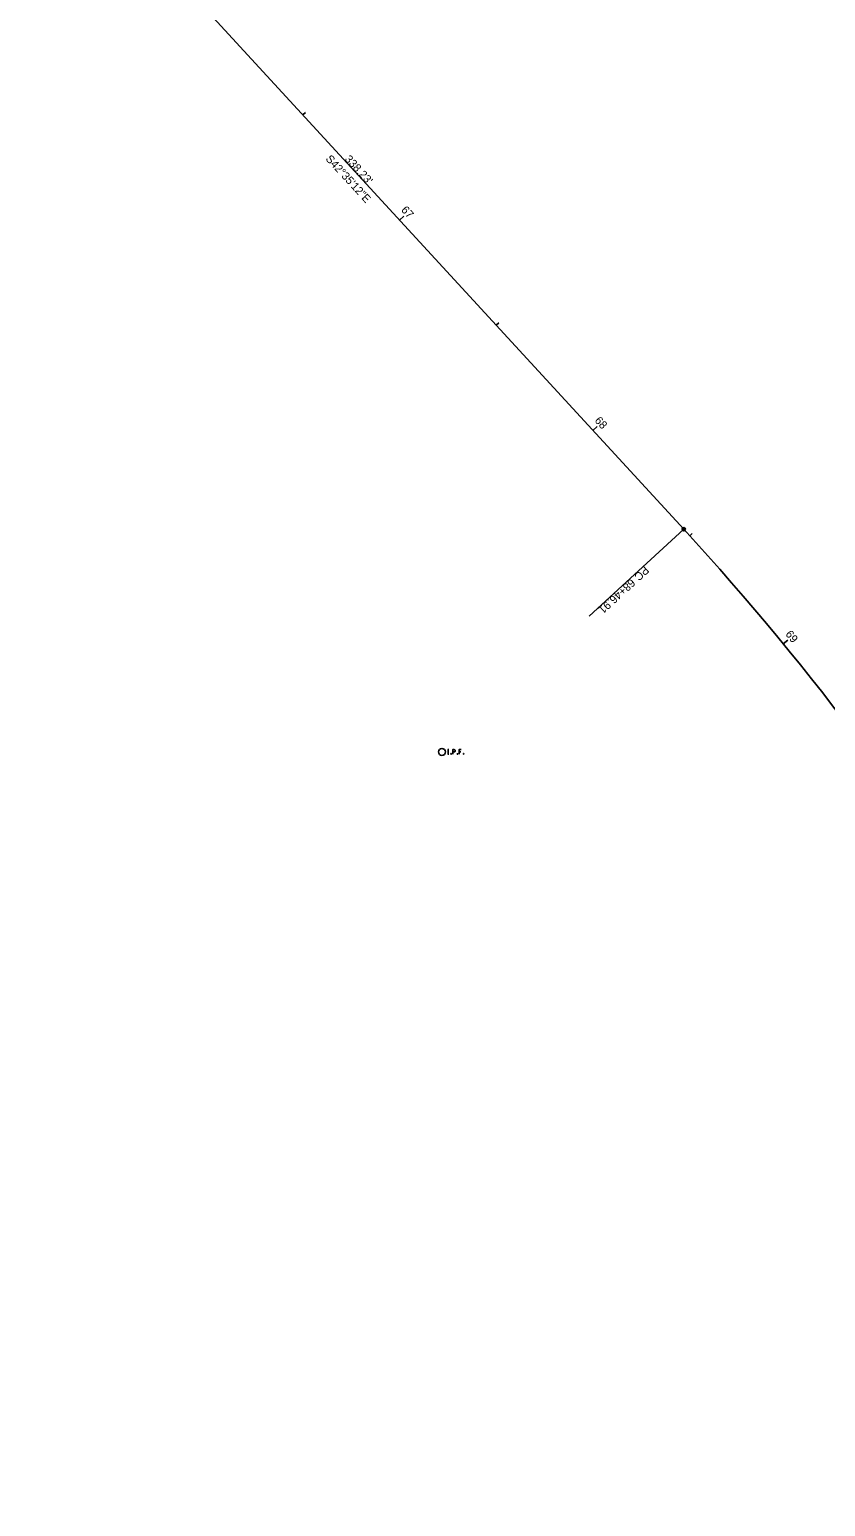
# Model space of a CAD drawing. Extents: x 1918148 to 1920349, y 624677 to 627727.
# Drawn here: x 1919025 to 1919304, y 624918 to 625435 of the extents above; entities that cross this region are included whole.
import ezdxf

# ---------------------------------------------------------------- set-up
doc = ezdxf.new("R2010")
doc.units = 0
for name, color, linetype in [('_CIVIL_CONSTRUCTION', 7, 'Continuous'), ('RS_Raster1', 7, 'Continuous'), ('RW_X_CL', 7, 'Continuous'), ('RW_X_CL_100_Cardinal_Points', 7, 'Continuous'), ('RW_X_CL_100_Curve_Data', 7, 'Continuous'), ('SV_X_Mon_Cells_Found', 7, 'Continuous')]:
    doc.layers.add(name, color=color, linetype=linetype)

msp = doc.modelspace()

# ---------------------------------------------------------------- linework, layer by layer
at = {"layer": 'RS_Raster1'}
msp.add_line((1919025.5, 625508.81), (1919254.38, 625259.79), dxfattribs=at)
msp.add_arc((1918551.3, 624613.58), 954.93, 18.58639, 42.58667, dxfattribs=at)
at = {"layer": 'RW_X_CL'}
msp.add_line((1919254.38, 625259.79), (1919221.25, 625229.34), dxfattribs=at)
msp.add_circle((1919254.38, 625259.79), 0.6, dxfattribs=at)
at = {"layer": 'RW_X_CL_100_Cardinal_Points'}
for p, q in [((1919121.13, 625404.76), (1919122.01, 625405.58)), ((1919154.96, 625367.95), (1919156.44, 625369.3)), ((1919188.8, 625331.14), (1919189.68, 625331.95)), ((1919222.63, 625294.33), (1919224.11, 625295.68)), ((1919256.47, 625257.51), (1919257.35, 625258.32)), ((1919289.2, 625219.72), (1919290.75, 625220.99))]:
    msp.add_line(p, q, dxfattribs=at)
at = {"layer": 'SV_X_Mon_Cells_Found'}
for points in [[(1919171.81, 625182.69), (1919172.17, 625182.69)], [(1919171.81, 625181.09), (1919172.17, 625181.09)], [(1919171.99, 625181.09), (1919171.99, 625182.69)], [(1919172.95, 625181.31), (1919173, 625181.31), (1919173.04, 625181.28), (1919173.07, 625181.23), (1919173.07, 625181.17), (1919173.04, 625181.12), (1919173, 625181.09), (1919172.95, 625181.09), (1919172.91, 625181.12), (1919172.88, 625181.17), (1919172.88, 625181.23), (1919172.91, 625181.28), (1919172.95, 625181.31)], [(1919173.55, 625181.09), (1919173.55, 625182.69), (1919174.08, 625182.69), (1919174.14, 625182.68), (1919174.22, 625182.66), (1919174.25, 625182.63), (1919174.28, 625182.61), (1919174.33, 625182.54), (1919174.36, 625182.48), (1919174.38, 625182.38), (1919174.38, 625182.23), (1919174.37, 625182.18), (1919174.35, 625182.1), (1919174.3, 625182.01), (1919174.26, 625181.98), (1919174.23, 625181.95), (1919174.17, 625181.93), (1919174.08, 625181.91), (1919173.55, 625181.91)], [(1919175.2, 625181.31), (1919175.25, 625181.31), (1919175.28, 625181.28), (1919175.32, 625181.23), (1919175.32, 625181.17), (1919175.28, 625181.12), (1919175.25, 625181.09), (1919175.2, 625181.09), (1919175.16, 625181.12), (1919175.13, 625181.17), (1919175.13, 625181.23), (1919175.16, 625181.28), (1919175.2, 625181.31)], [(1919176.56, 625182.69), (1919175.8, 625182.69), (1919175.8, 625181.09)], [(1919175.8, 625181.91), (1919176.34, 625181.91)], [(1919177.35, 625181.31), (1919177.4, 625181.31), (1919177.43, 625181.28), (1919177.47, 625181.23), (1919177.47, 625181.17), (1919177.43, 625181.12), (1919177.4, 625181.09), (1919177.35, 625181.09), (1919177.31, 625181.12), (1919177.28, 625181.17), (1919177.28, 625181.23), (1919177.31, 625181.28), (1919177.35, 625181.31)]]:
    msp.add_lwpolyline(points, dxfattribs=at)
msp.add_circle((1919169.8, 625181.9), 1.2, dxfattribs=at)

# ---------------------------------------------------------------- texts
at = {"layer": '_CIVIL_CONSTRUCTION'}
msp.add_text('S42°35\'12"E', height=2.8, rotation=312.5867, dxfattribs=at).set_placement((1919128.91, 625389.2))
at = {"layer": 'RW_X_CL'}
for s, p in [('PC', (1919240.66, 625247.11)), ('68+46.91', (1919235.85, 625242.7))]:
    msp.add_text(s, height=2.8, rotation=222.5867, dxfattribs=at).set_placement(p)
at = {"layer": 'RW_X_CL_100_Cardinal_Points'}
for s, rotation, p in [('67', 312.5867, (1919155.32, 625371.33)), ('68', 312.5867, (1919223.03, 625297.66)), ('69', 309.4012, (1919289.79, 625223.01))]:
    msp.add_text(s, height=2.8, rotation=rotation, dxfattribs=at).set_placement(p)
at = {"layer": 'RW_X_CL_100_Curve_Data'}
msp.add_text("338.23'", height=2.8, rotation=312.5867, dxfattribs=at).set_placement((1919135.58, 625389.11))

doc.saveas('drawing.dxf')
